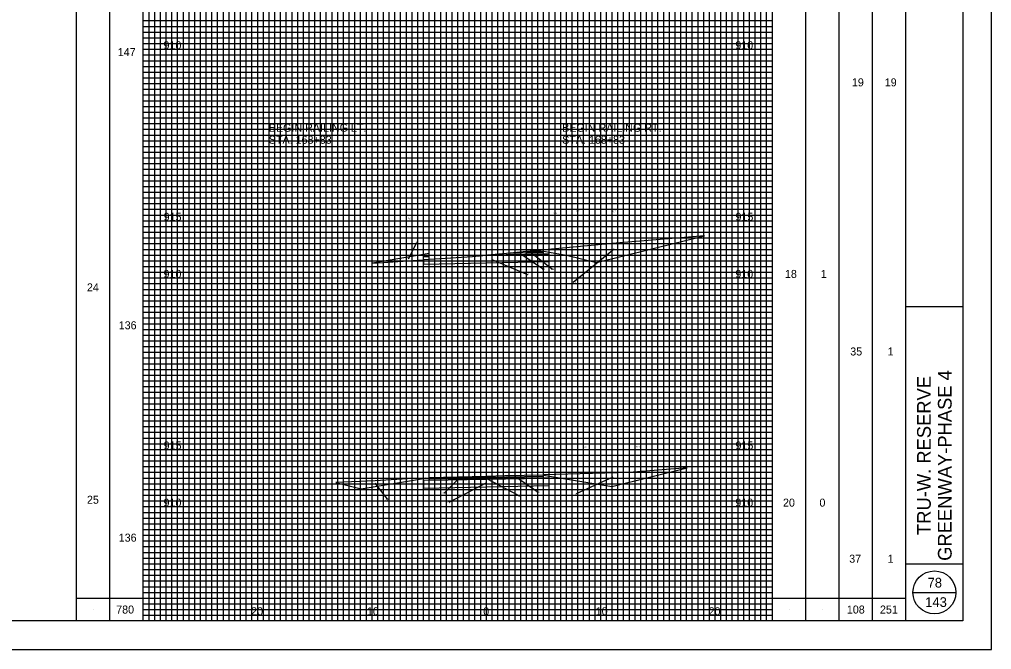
# Model space of a CAD drawing. Extents: x -73 to 160, y -2 to 1877.
# Drawn here: x 75 to 160, y 457.5 to 512.6 of the extents above; entities that cross this region are included whole.
import ezdxf

# ---------------------------------------------------------------- set-up
doc = ezdxf.new("R2010")
doc.units = 0
for name, color, linetype in [('DR_P_Flood_Boundary', 7, 'Continuous'), ('GK_Cells', 7, 'Continuous'), ('RD_X_Fence', 7, 'Continuous'), ('TX_X_5', 7, 'Continuous'), ('UT_P_Water_Cells', 7, 'Continuous'), ('XS_P_Pavt_Layers', 7, 'Continuous'), ('XS_P_Pavt_Surface', 7, 'Continuous'), ('XS_X_Ground_Line', 7, 'Continuous')]:
    doc.layers.add(name, color=color, linetype=linetype)

msp = doc.modelspace()

# ---------------------------------------------------------------- linework, layer by layer
at = {"layer": 'DR_P_Flood_Boundary'}
for p, q in [((90.832, 460), (90.832, 565)), ((95.832, 460), (95.832, 565)), ((100.832, 460), (100.832, 565)), ((105.832, 460), (105.832, 565)), ((110.832, 460), (110.832, 565)), ((115.832, 460), (115.832, 565)), ((120.832, 460), (120.832, 565)), ((125.832, 460), (125.832, 565)), ((130.832, 460), (130.832, 565)), ((135.832, 460), (135.832, 565)), ((85.832, 510), (140.832, 510)), ((85.832, 505), (140.832, 505)), ((85.832, 500), (140.832, 500)), ((85.832, 495), (140.832, 495)), ((85.832, 490), (140.832, 490)), ((85.832, 485), (140.832, 485)), ((85.832, 480), (140.832, 480)), ((85.832, 475), (140.832, 475)), ((85.832, 470), (140.832, 470)), ((85.832, 465), (140.832, 465))]:
    msp.add_line(p, q, dxfattribs=at)
at = {"layer": 'GK_Cells'}
for p, q in [((152.5, 460), (152.5, 565)), ((152.5, 487.5), (157.5, 487.5)), ((152.5, 465), (157.5, 465))]:
    msp.add_line(p, q, dxfattribs=at)
msp.add_lwpolyline([(0, 565), (157.5, 565), (157.5, 460), (0, 460)], close=True, dxfattribs=at)
at = {"layer": 'RD_X_Fence'}
for p, q in [((109.011, 491.677), (109.747, 493.112)), ((125.469, 491.338), (134.897, 493.695)), ((117.911, 492.167), (115.924, 491.982)), ((119.33, 492.3), (117.911, 492.167)), ((120.832, 492.226), (117.911, 492.167)), ((117.911, 492.167), (118.831, 492.186)), ((118.831, 492.186), (120.832, 492.226)), ((119.33, 492.3), (120.832, 492.33)), ((120.832, 492.33), (119.33, 492.3)), ((119.688, 492.249), (121.62, 490.769)), ((120.832, 492.33), (122.832, 491.997)), ((120.832, 492.226), (120.832, 492.33)), ((120.832, 492.08), (120.832, 492.226)), ((126.999, 492.502), (123.419, 489.597)), ((110.832, 492.13), (105.873, 491.303)), ((105.873, 491.303), (110.332, 491.587)), ((110.332, 491.87), (110.832, 491.88)), ((110.332, 491.587), (110.332, 491.87)), ((110.332, 491.587), (110.332, 491.203)), ((110.332, 491.203), (121.332, 491.423)), ((115.924, 491.982), (120.832, 492.08)), ((116.307, 491.624), (119.427, 490.29)), ((118.833, 492.107), (120.831, 490.768)), ((121.332, 491.423), (121.332, 492.09)), ((122.832, 491.997), (125.469, 491.338)), ((117.455, 472.683), (115.833, 472.64)), ((115.834, 472.547), (120.832, 472.647)), ((120.832, 472.751), (117.455, 472.683)), ((118.367, 472.649), (120.361, 471.256)), ((128.308, 472.974), (120.832, 472.774)), ((120.832, 472.647), (120.832, 472.751)), ((120.832, 472.751), (126.787, 471.759)), ((120.832, 472.501), (120.832, 472.647)), ((126.787, 471.759), (133.381, 473.407)), ((133.381, 473.407), (128.308, 472.974)), ((102.659, 472.113), (104.878, 471.559)), ((104.878, 471.559), (110.511, 472.497)), ((106.071, 472.057), (107.171, 470.617)), ((110.511, 472.497), (109.4, 472.468)), ((110.832, 472.301), (110.332, 472.291)), ((110.332, 472.291), (110.332, 471.624)), ((110.332, 471.624), (121.332, 471.844)), ((110.832, 472.447), (115.834, 472.547)), ((110.832, 472.506), (110.832, 472.447)), ((110.832, 472.301), (120.832, 472.501)), ((110.832, 472.447), (110.832, 472.301)), ((113.519, 472.539), (112.141, 471.17)), ((115.832, 472.068), (112.542, 470.372)), ((115.832, 472.474), (118.73, 470.947)), ((121.332, 471.844), (121.332, 472.511)), ((126.883, 472.582), (123.687, 471.105))]:
    msp.add_line(p, q, dxfattribs=at)
for points in [[(134.897, 493.695), (127.496, 493.063), (119.33, 492.3)], [(115.924, 491.982), (115.832, 491.973), (114.602, 491.858), (110.332, 491.587)], [(110.832, 491.88), (110.832, 492.026), (110.832, 492.13)], [(121.332, 492.09), (120.832, 492.08), (115.924, 491.982)], [(120.832, 472.647), (115.834, 472.547), (110.832, 472.447)], [(115.833, 472.64), (110.834, 472.506), (110.832, 472.506)], [(115.834, 472.547), (115.833, 472.64)], [(115.833, 472.64), (115.834, 472.547)], [(120.832, 472.774), (120.832, 472.751)], [(109.4, 472.468), (106.103, 472.257), (102.659, 472.113)], [(121.332, 472.511), (120.832, 472.501), (110.832, 472.301)]]:
    msp.add_lwpolyline(points, dxfattribs=at)
at = {"layer": 'TX_X_5'}
msp.add_lwpolyline([(-10, 457.5), (160, 457.5), (160, 567.5), (-10, 567.5)], close=True, dxfattribs=at)
at = {"layer": 'UT_P_Water_Cells'}
for p, q in [((86.332, 460), (86.332, 565)), ((86.832, 460), (86.832, 565)), ((87.332, 460), (87.332, 565)), ((87.832, 460), (87.832, 565)), ((88.332, 460), (88.332, 565)), ((88.832, 460), (88.832, 565)), ((89.332, 460), (89.332, 565)), ((89.832, 460), (89.832, 565)), ((90.332, 460), (90.332, 565)), ((91.332, 460), (91.332, 565)), ((91.832, 460), (91.832, 565)), ((92.332, 460), (92.332, 565)), ((92.832, 460), (92.832, 565)), ((93.332, 460), (93.332, 565)), ((93.832, 460), (93.832, 565)), ((94.332, 460), (94.332, 565)), ((94.832, 460), (94.832, 565)), ((95.332, 460), (95.332, 565)), ((96.332, 460), (96.332, 565)), ((96.832, 460), (96.832, 565)), ((97.332, 460), (97.332, 565)), ((97.832, 460), (97.832, 565)), ((98.332, 460), (98.332, 565)), ((98.832, 460), (98.832, 565)), ((99.332, 460), (99.332, 565)), ((99.832, 460), (99.832, 565)), ((100.332, 460), (100.332, 565)), ((101.332, 460), (101.332, 565)), ((101.832, 460), (101.832, 565)), ((102.332, 460), (102.332, 565)), ((102.832, 460), (102.832, 565)), ((103.332, 460), (103.332, 565)), ((103.832, 460), (103.832, 565)), ((104.332, 460), (104.332, 565)), ((104.832, 460), (104.832, 565)), ((105.332, 460), (105.332, 565)), ((106.332, 460), (106.332, 565)), ((106.832, 460), (106.832, 565)), ((107.332, 460), (107.332, 565)), ((107.832, 460), (107.832, 565)), ((108.332, 460), (108.332, 565)), ((108.832, 460), (108.832, 565)), ((109.332, 460), (109.332, 565)), ((109.832, 460), (109.832, 565)), ((110.332, 460), (110.332, 565)), ((111.332, 460), (111.332, 565)), ((111.832, 460), (111.832, 565)), ((112.332, 460), (112.332, 565)), ((112.832, 460), (112.832, 565)), ((113.332, 460), (113.332, 565)), ((113.832, 460), (113.832, 565)), ((114.332, 460), (114.332, 565)), ((114.832, 460), (114.832, 565)), ((115.332, 460), (115.332, 565)), ((116.332, 460), (116.332, 565)), ((116.832, 460), (116.832, 565)), ((117.332, 460), (117.332, 565)), ((117.832, 460), (117.832, 565)), ((118.332, 460), (118.332, 565)), ((118.832, 460), (118.832, 565)), ((119.332, 460), (119.332, 565)), ((119.832, 460), (119.832, 565)), ((120.332, 460), (120.332, 565)), ((121.332, 460), (121.332, 565)), ((121.832, 460), (121.832, 565)), ((122.332, 460), (122.332, 565)), ((122.832, 460), (122.832, 565)), ((123.332, 460), (123.332, 565)), ((123.832, 460), (123.832, 565)), ((124.332, 460), (124.332, 565)), ((124.832, 460), (124.832, 565)), ((125.332, 460), (125.332, 565)), ((126.332, 460), (126.332, 565)), ((126.832, 460), (126.832, 565)), ((127.332, 460), (127.332, 565)), ((127.832, 460), (127.832, 565)), ((128.332, 460), (128.332, 565)), ((128.832, 460), (128.832, 565)), ((129.332, 460), (129.332, 565)), ((129.832, 460), (129.832, 565)), ((130.332, 460), (130.332, 565)), ((131.332, 460), (131.332, 565)), ((131.832, 460), (131.832, 565)), ((132.332, 460), (132.332, 565)), ((132.832, 460), (132.832, 565)), ((133.332, 460), (133.332, 565)), ((133.832, 460), (133.832, 565)), ((134.332, 460), (134.332, 565)), ((134.832, 460), (134.832, 565)), ((135.332, 460), (135.332, 565)), ((136.332, 460), (136.332, 565)), ((136.832, 460), (136.832, 565)), ((137.332, 460), (137.332, 565)), ((137.832, 460), (137.832, 565)), ((138.332, 460), (138.332, 565)), ((138.832, 460), (138.832, 565)), ((139.332, 460), (139.332, 565)), ((139.832, 460), (139.832, 565)), ((140.332, 460), (140.332, 565)), ((85.832, 512.5), (140.832, 512.5)), ((85.832, 512), (140.832, 512)), ((85.832, 511.5), (140.832, 511.5)), ((85.832, 511), (140.832, 511)), ((85.832, 510.5), (140.832, 510.5)), ((85.832, 509.5), (140.832, 509.5)), ((85.832, 509), (140.832, 509)), ((85.832, 508.5), (140.832, 508.5)), ((85.832, 508), (140.832, 508)), ((85.832, 507.5), (140.832, 507.5)), ((85.832, 507), (140.832, 507)), ((85.832, 506.5), (140.832, 506.5)), ((85.832, 506), (140.832, 506)), ((85.832, 505.5), (140.832, 505.5)), ((85.832, 504.5), (140.832, 504.5)), ((85.832, 504), (140.832, 504)), ((85.832, 503.5), (140.832, 503.5)), ((85.832, 503), (140.832, 503)), ((85.832, 502.5), (140.832, 502.5)), ((85.832, 502), (140.832, 502)), ((85.832, 501.5), (140.832, 501.5)), ((85.832, 501), (140.832, 501)), ((85.832, 500.5), (140.832, 500.5)), ((85.832, 499.5), (140.832, 499.5)), ((85.832, 499), (140.832, 499)), ((85.832, 498.5), (140.832, 498.5)), ((85.832, 498), (140.832, 498)), ((85.832, 497.5), (140.832, 497.5)), ((85.832, 497), (140.832, 497)), ((85.832, 496.5), (140.832, 496.5)), ((85.832, 496), (140.832, 496)), ((85.832, 495.5), (140.832, 495.5)), ((85.832, 494.5), (140.832, 494.5)), ((85.832, 494), (140.832, 494)), ((85.832, 493.5), (140.832, 493.5)), ((85.832, 493), (140.832, 493)), ((85.832, 492.5), (140.832, 492.5)), ((85.832, 492), (140.832, 492)), ((85.832, 491.5), (140.832, 491.5)), ((85.832, 491), (140.832, 491)), ((85.832, 490.5), (140.832, 490.5)), ((85.832, 489.5), (140.832, 489.5)), ((85.832, 489), (140.832, 489)), ((85.832, 488.5), (140.832, 488.5)), ((85.832, 488), (140.832, 488)), ((85.832, 487.5), (140.832, 487.5)), ((85.832, 487), (140.832, 487)), ((85.832, 486.5), (140.832, 486.5)), ((85.832, 486), (140.832, 486)), ((85.832, 485.5), (140.832, 485.5)), ((85.832, 484.5), (140.832, 484.5)), ((85.832, 484), (140.832, 484)), ((85.832, 483.5), (140.832, 483.5)), ((85.832, 483), (140.832, 483)), ((85.832, 482.5), (140.832, 482.5)), ((85.832, 482), (140.832, 482)), ((85.832, 481.5), (140.832, 481.5)), ((85.832, 481), (140.832, 481)), ((85.832, 480.5), (140.832, 480.5)), ((85.832, 479.5), (140.832, 479.5)), ((85.832, 479), (140.832, 479)), ((85.832, 478.5), (140.832, 478.5)), ((85.832, 478), (140.832, 478)), ((85.832, 477.5), (140.832, 477.5)), ((85.832, 477), (140.832, 477)), ((85.832, 476.5), (140.832, 476.5)), ((85.832, 476), (140.832, 476)), ((85.832, 475.5), (140.832, 475.5)), ((85.832, 474.5), (140.832, 474.5)), ((85.832, 474), (140.832, 474)), ((85.832, 473.5), (140.832, 473.5)), ((85.832, 473), (140.832, 473)), ((85.832, 472.5), (140.832, 472.5)), ((85.832, 472), (140.832, 472)), ((85.832, 471.5), (140.832, 471.5)), ((85.832, 471), (140.832, 471)), ((85.832, 470.5), (140.832, 470.5)), ((85.832, 469.5), (140.832, 469.5)), ((85.832, 469), (140.832, 469)), ((85.832, 468.5), (140.832, 468.5)), ((85.832, 468), (140.832, 468)), ((85.832, 467.5), (140.832, 467.5)), ((85.832, 467), (140.832, 467)), ((85.832, 466.5), (140.832, 466.5)), ((85.832, 466), (140.832, 466)), ((85.832, 465.5), (140.832, 465.5)), ((85.832, 464.5), (140.832, 464.5)), ((85.832, 464), (140.832, 464)), ((85.832, 463.5), (140.832, 463.5)), ((85.832, 463), (140.832, 463)), ((85.832, 462.5), (140.832, 462.5)), ((85.832, 462), (140.832, 462)), ((85.832, 461.5), (140.832, 461.5)), ((85.832, 461), (140.832, 461)), ((85.832, 460.5), (140.832, 460.5))]:
    msp.add_line(p, q, dxfattribs=at)
at = {"layer": 'XS_X_Ground_Line'}
for p, q in [((80, 460), (80, 565)), ((85.832, 460), (85.832, 565)), ((140.832, 460), (140.832, 565)), ((146.667, 460), (146.667, 565)), ((82.916, 460), (82.916, 563.75)), ((143.75, 460), (143.75, 563.75)), ((149.583, 460), (149.583, 563.75)), ((155, 476.458), (155, 476.458)), ((153.125, 462.5), (156.875, 462.5)), ((155, 462.925), (155, 462.925)), ((80, 462), (85.832, 462)), ((140.832, 462), (152.5, 462)), ((81.458, 461.03), (81.458, 461.03)), ((84.374, 461.03), (84.374, 461.03)), ((142.291, 461), (142.291, 461)), ((145.209, 461), (145.209, 461)), ((148.125, 461), (148.125, 461)), ((151.042, 461), (151.042, 461)), ((155, 461.225), (155, 461.225))]:
    msp.add_line(p, q, dxfattribs=at)
msp.add_circle((155, 462.5), 1.875, dxfattribs=at)

# ---------------------------------------------------------------- texts
at = {"layer": 'RD_X_Fence'}
for s, p in [('2.0', (121.707, 495.601)), ('2.7', (123.69, 495.763)), ('9.7', (126.866, 495.743)), ('5.0', (108.951, 495.12)), ('1.1', (109.655, 493.042)), ('0.6', (120.674, 490.698)), ('0.2', (121.468, 490.699)), ('6.5', (119.28, 490.22)), ('11.0', (123.261, 489.527)), ('6.0', (124.316, 475.124)), ('6.8', (128.935, 475.174)), ('2.3', (103.923, 474.913)), ('6.0', (107.012, 474.954)), ('0.4', (111.989, 471.1)), ('1.5', (118.611, 470.877)), ('0.5', (120.209, 471.186)), ('7.2', (123.543, 471.035)), ('2.6', (107.021, 470.547)), ('7.3', (112.397, 470.302))]:
    msp.add_text(s, height=0.14, dxfattribs=at).set_placement(p)
at = {"layer": 'XS_P_Pavt_Layers'}
for s, p in [('78', (154.404, 462.925)), ('143', (154.197, 461.225))]:
    msp.add_text(s, height=0.85, dxfattribs=at).set_placement(p)
at = {"layer": 'XS_P_Pavt_Surface'}
for s, p in [('147', (83.6, 509.406)), ('910', (87.598, 510)), ('910', (137.598, 510)), ('19', (147.79, 506.754)), ('19', (150.662, 506.754)), ('BEGIN RAILING LT.', (96.808, 502.784)), ('BEGIN RAILING RT.', (122.456, 502.784)), ('STA. 168+83', (96.808, 501.734)), ('STA. 168+83', (122.456, 501.734)), ('915', (87.609, 495)), ('915', (137.609, 495)), ('910', (87.598, 490)), ('910', (137.598, 490)), ('18', (141.935, 490)), ('1', (145.065, 490)), ('24', (80.899, 488.827)), ('136', (83.68, 485.51)), ('35', (147.644, 483.219)), ('1', (150.912, 483.219)), ('915', (87.609, 475)), ('915', (137.609, 475)), ('25', (80.904, 470.254)), ('910', (87.598, 470)), ('910', (137.598, 470)), ('20', (141.764, 470)), ('0', (144.95, 470)), ('136', (83.68, 466.937)), ('37', (147.553, 465.096)), ('1', (150.912, 465.096)), ('780', (83.46, 460.65)), ('20', (95.257, 460.5)), ('10', (105.389, 460.5)), ('0', (115.554, 460.5)), ('0', (115.554, 460.5)), ('10', (125.389, 460.5)), ('20', (135.257, 460.5)), ('108', (147.348, 460.65)), ('251', (150.242, 460.65))]:
    msp.add_text(s, height=0.7, dxfattribs=at).set_placement(p)
for s, p in [('TRU-W. RESERVE', (154.688, 467.519)), ('GREENWAY-PHASE 4', (156.512, 465.261))]:
    msp.add_text(s, height=1.2, rotation=90, dxfattribs=at).set_placement(p)
at = {"layer": 'XS_X_Ground_Line'}
msp.add_text('143', height=0.85, dxfattribs=at).set_placement((154.197, 461.225))

doc.saveas('drawing.dxf')
